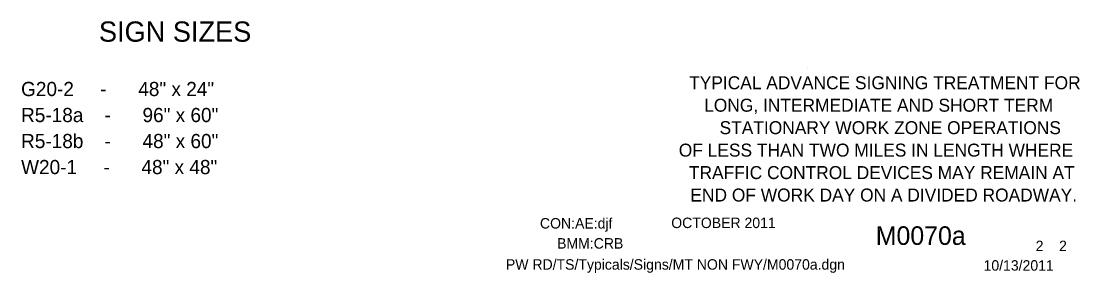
# Model space of a CAD drawing. Extents: x 19017 to 20754, y 4888 to 6104.
# Drawn here: x 20091 to 20717, y 5121 to 5270 of the extents above; entities that cross this region are included whole.
import ezdxf

# ---------------------------------------------------------------- set-up
doc = ezdxf.new("R2010")
doc.units = 0
for name, color, linetype in [('BORDER', 7, 'Continuous'), ('BORDER_SIGNAL_WO', 7, 'Continuous'), ('TYPICAL_TEXT_DIMEN_PR', 7, 'Continuous')]:
    doc.layers.add(name, color=color, linetype=linetype)

msp = doc.modelspace()

# ---------------------------------------------------------------- linework, layer by layer
at = {"layer": 'BORDER'}
for p, q in [((20555.753, 5241.887), (20555.753, 5241.887)), ((20555.753, 5241.887), (20555.753, 5241.887)), ((20596.417, 5194.208), (20596.417, 5194.208)), ((20596.417, 5194.208), (20596.417, 5194.208))]:
    msp.add_line(p, q, dxfattribs=at)

# ---------------------------------------------------------------- texts
at = {"layer": 'BORDER_SIGNAL_WO'}
for s, height, p in [('TYPICAL ADVANCE SIGNING TREATMENT FOR', 7.67305, (20486.026, 5229.706)), ('LONG, INTERMEDIATE AND SHORT TERM ', 7.67305, (20494.916, 5216.418)), ('STATIONARY WORK ZONE OPERATIONS', 7.67305, (20504.032, 5203.131)), ('OF LESS THAN TWO MILES IN LENGTH WHERE ', 7.67305, (20479.917, 5189.843)), ('TRAFFIC CONTROL DEVICES MAY REMAIN AT', 7.67305, (20485.916, 5176.555)), (' END OF WORK DAY ON A DIVIDED ROADWAY.', 7.67305, (20483.926, 5163.268)), ('CON:AE:djf', 6.2, (20397.854, 5147.266)), ('    OCTOBER 2011    ', 6.2, (20466.248, 5147.547)), ('    M0070a   ', 11, (20580.029, 5137.588)), ('BMM:CRB   ', 6.2, (20407.977, 5135.382)), (' 2    2 ', 6.2, (20688.613, 5133.906)), ('PW RD/TS/Typicals/Signs/MT NON FWY/M0070a.dgn  ', 6.2, (20377.721, 5122.919)), ('10/13/2011    ', 6.19999, (20660.095, 5122.338))]:
    msp.add_text(s, height=height, dxfattribs=at).set_placement(p)
at = {"layer": 'TYPICAL_TEXT_DIMEN_PR'}
for s, height, p in [('SIGN SIZES', 12, (20137.109, 5257.831)), ('G20-2     -      48" x 24"', 8.4, (20091.089, 5225.659)), ('R5-18a    -      96" x 60"', 8.4, (20091.089, 5210.259)), ('R5-18b    -      48" x 60"', 8.4, (20091.089, 5194.859)), ('W20-1     -      48" x 48"', 8.4, (20091.089, 5179.459))]:
    msp.add_text(s, height=height, dxfattribs=at).set_placement(p)

doc.saveas('drawing.dxf')
